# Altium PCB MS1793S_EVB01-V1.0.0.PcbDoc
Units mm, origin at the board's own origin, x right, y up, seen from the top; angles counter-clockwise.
Board outline 52.93 x 27.69 mm, 2 copper layers (Top Layer, Bottom Layer); 34 components, 26 nets, 126 pads, 278 vias.
Unrouted connection lines stored in the file: 2.
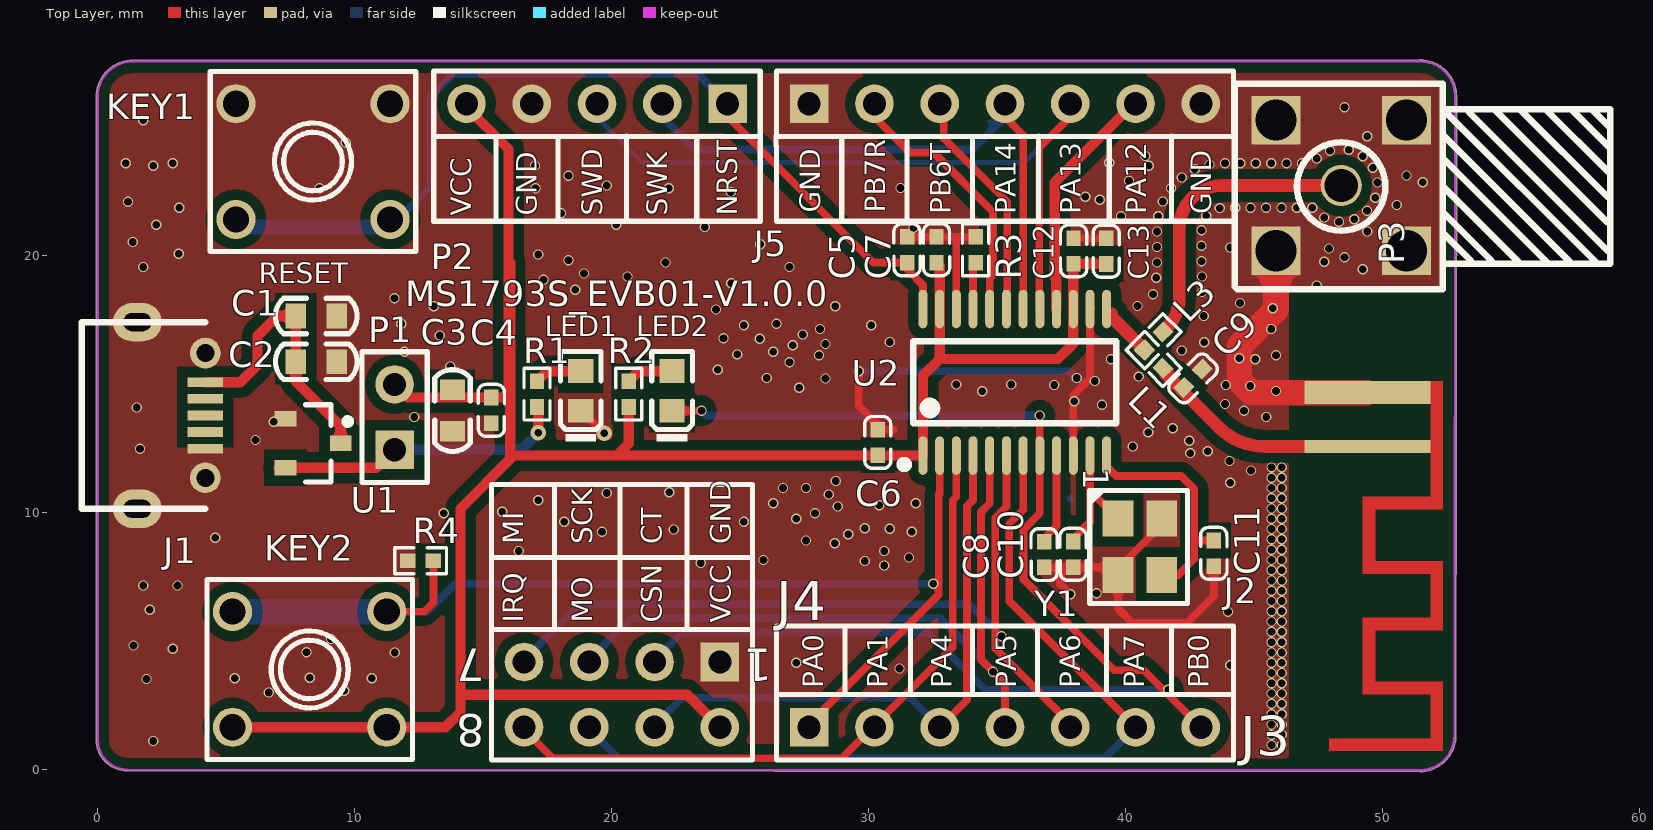
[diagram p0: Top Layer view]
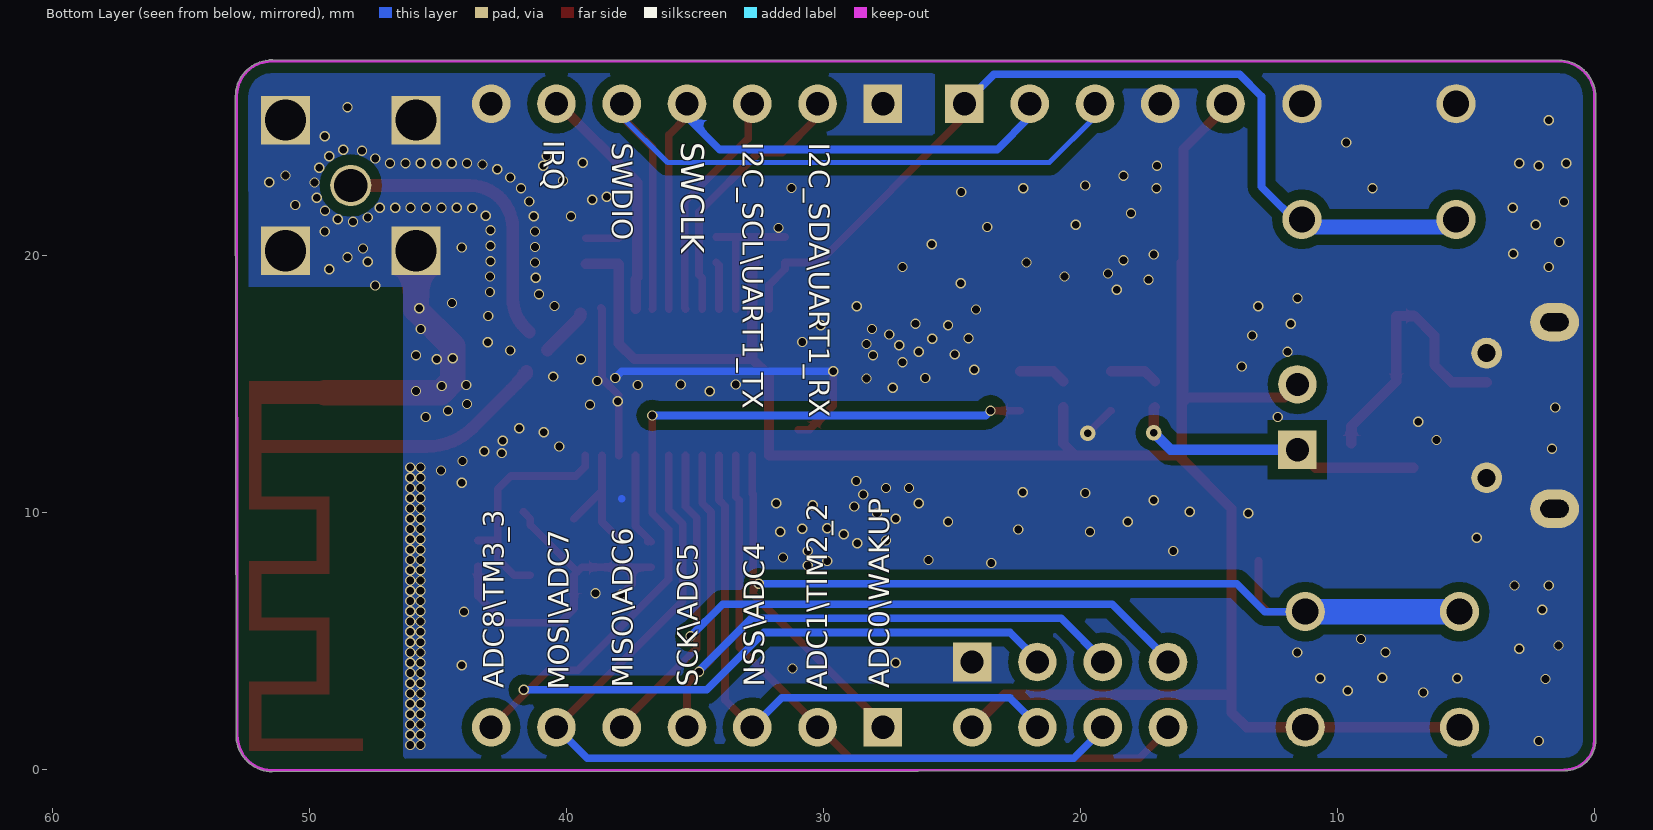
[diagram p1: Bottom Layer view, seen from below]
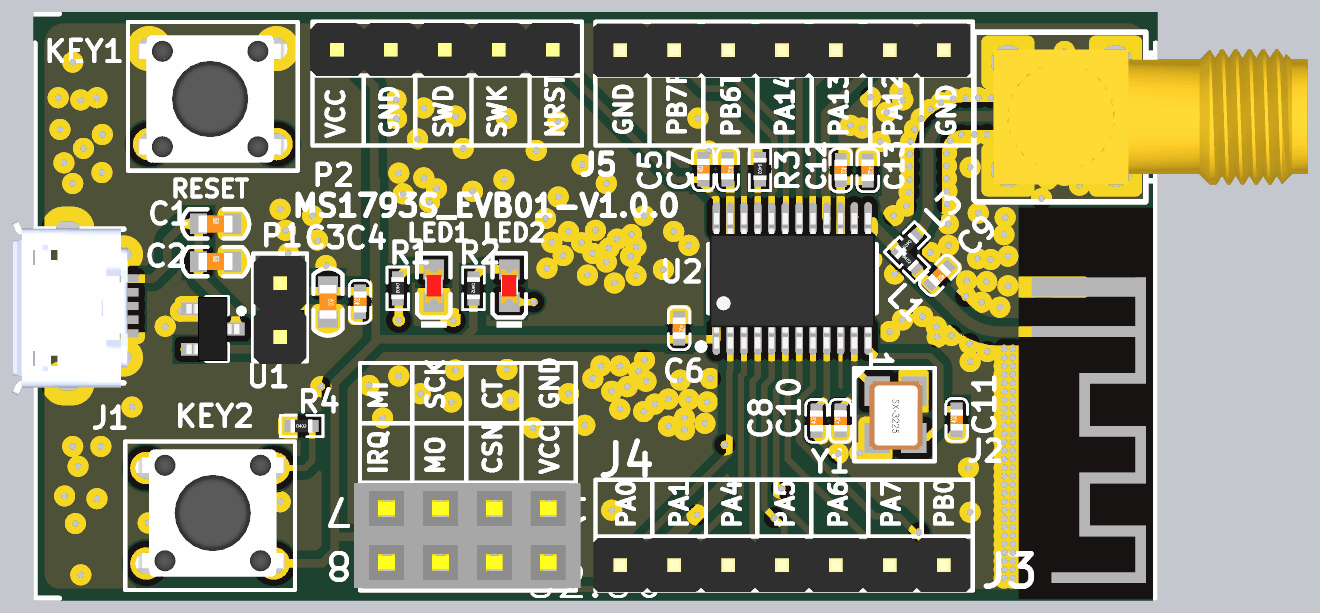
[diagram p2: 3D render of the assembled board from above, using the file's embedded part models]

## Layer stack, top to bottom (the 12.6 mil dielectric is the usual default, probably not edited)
Top Solder: solder mask 0.0102, Solder Resist, Dk 3.5
Top Layer: signal copper 0.0356
Dielectric 1: dielectric 0.32, FR-4, Dk 4.8
Bottom Layer: signal copper 0.0356
Bottom Solder: solder mask 0.0102, Solder Resist, Dk 3.5

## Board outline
-0.051,1.151 cw(c-0.001,1.151) -0.05,1.159 -0.051,26.162 cw(c-0.001,26.162) -0.051,26.168 cw(c1.366,26.188) 1.366,27.604 cw(c1.366,27.554) 1.372,27.604 51.428,27.609 cw(c51.429,27.559) 51.428,27.609 cw(c51.461,26.193) 51.493,27.609 51.562,27.609 cw(c51.562,27.559) 51.584,27.604 cw(c51.461,26.193) 52.877,26.193 cw(c52.827,26.193) 52.877,26.193 52.851,1.361 cw(c51.435,1.334) 52.851,1.334 cw(c51.435,1.334) 52.851,1.303 52.851,1.264 cw(c52.801,1.264) 52.849,1.25 cw(c51.435,1.334) 51.435,-0.083 cw(c51.435,-0.032) 51.435,-0.083 1.143,-0.051 cw(c1.143,0) 1.14,-0.051 cw(c1.151,1.151)

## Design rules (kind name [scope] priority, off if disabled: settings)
Clearance [All] p1: gap=0.25
ComponentClearance [All] p1 off: gap=0.254 collisioncheckmode=3 verticalgap=0.254 showdistances=FALSE
HoleToHoleClearance [All] p1: gap=0 allowstackedmicrovias=FALSE
MinimumSolderMaskSliver [All] p1 off: minsoldermaskwidth=0
PlaneConnect [All] p1: planeconnectstyle=Direct reliefexpansion=0.508 reliefentries=4 reliefconductorwidth=0.254 reliefairgap=0.254
PolygonConnect PolygonConnect_27 [All vs IsNamedPolygon('GND_L01_P042')] p1: connectstyle=Direct reliefconductorwidth=0.254 reliefentries=4 polygonreliefangle="90 Angle" airgapwidth=0.254
PolygonConnect PolygonConnect_26 [All vs IsNamedPolygon('GND_L02_P044')] p2: connectstyle=Direct reliefconductorwidth=0.254 reliefentries=4 polygonreliefangle="90 Angle" airgapwidth=0.254
PolygonConnect PolygonConnect_25 [All vs IsNamedPolygon('GND_L02_P026')] p3: connectstyle=Direct reliefconductorwidth=0.254 reliefentries=4 polygonreliefangle="90 Angle" airgapwidth=0.254
PolygonConnect PolygonConnect_24 [All vs IsNamedPolygon('GND_L01_P028')] p4: connectstyle=Direct reliefconductorwidth=0.254 reliefentries=4 polygonreliefangle="90 Angle" airgapwidth=0.254
PolygonConnect PolygonConnect_23 [All vs IsNamedPolygon('GND_L02_P022')] p5: connectstyle=Direct reliefconductorwidth=0.254 reliefentries=4 polygonreliefangle="90 Angle" airgapwidth=0.254
PolygonConnect PolygonConnect_22 [All vs IsNamedPolygon('GND_L01_P020')] p6: connectstyle=Direct reliefconductorwidth=0.254 reliefentries=4 polygonreliefangle="90 Angle" airgapwidth=0.254
PolygonConnect PolygonConnect_21 [All vs IsNamedPolygon('GND_L02_P016')] p7: connectstyle=Direct reliefconductorwidth=0.254 reliefentries=4 polygonreliefangle="90 Angle" airgapwidth=0.254
PolygonConnect PolygonConnect_20 [All vs IsNamedPolygon('GND_L01_P018')] p8: connectstyle=Direct reliefconductorwidth=0.254 reliefentries=4 polygonreliefangle="90 Angle" airgapwidth=0.254
PolygonConnect PolygonConnect_19 [All vs IsNamedPolygon('GND_L02_P014')] p9: connectstyle=Direct reliefconductorwidth=0.254 reliefentries=4 polygonreliefangle="90 Angle" airgapwidth=0.254
PolygonConnect PolygonConnect_18 [All vs IsNamedPolygon('GND_L01_P012')] p10: connectstyle=Direct reliefconductorwidth=0.254 reliefentries=4 polygonreliefangle="90 Angle" airgapwidth=0.254
PolygonConnect PolygonConnect_17 [All vs IsNamedPolygon('GND_L02_P010')] p11: connectstyle=Direct reliefconductorwidth=0.254 reliefentries=4 polygonreliefangle="90 Angle" airgapwidth=0.254
PolygonConnect PolygonConnect_16 [All vs IsNamedPolygon('GND_L01_P008')] p12: connectstyle=Direct reliefconductorwidth=0.254 reliefentries=4 polygonreliefangle="90 Angle" airgapwidth=0.254
PolygonConnect PolygonConnect_15 [All vs IsNamedPolygon('GND_L02_P010')] p13: connectstyle=Relief reliefconductorwidth=0.254 reliefentries=4 polygonreliefangle="45 Angle" airgapwidth=0.254
PolygonConnect PolygonConnect_14 [All vs IsNamedPolygon('GND_L01_P008')] p14: connectstyle=Relief reliefconductorwidth=0.254 reliefentries=4 polygonreliefangle="45 Angle" airgapwidth=0.254
PolygonConnect PolygonConnect_13 [All vs IsNamedPolygon('GND_L02_P010')] p15: connectstyle=Relief reliefconductorwidth=0.254 reliefentries=4 polygonreliefangle="45 Angle" airgapwidth=0.254
PolygonConnect PolygonConnect_12 [All vs IsNamedPolygon('GND_L01_P008')] p16: connectstyle=Relief reliefconductorwidth=0.254 reliefentries=4 polygonreliefangle="45 Angle" airgapwidth=0.254
PolygonConnect PolygonConnect_11 [All vs IsNamedPolygon('GND_L02_P006')] p17: connectstyle=Direct reliefconductorwidth=0.254 reliefentries=4 polygonreliefangle="90 Angle" airgapwidth=0.254
PolygonConnect PolygonConnect_10 [All vs IsNamedPolygon('GND_L01_P004')] p18: connectstyle=Direct reliefconductorwidth=0.254 reliefentries=4 polygonreliefangle="90 Angle" airgapwidth=0.254
PolygonConnect PolygonConnect_9 [All vs IsNamedPolygon('GND_L01_P004')] p19: connectstyle=Relief reliefconductorwidth=0.254 reliefentries=4 polygonreliefangle="45 Angle" airgapwidth=0.254
PolygonConnect PolygonConnect_8 [All vs IsNamedPolygon('GND_L02_P006')] p20: connectstyle=Relief reliefconductorwidth=0.254 reliefentries=4 polygonreliefangle="45 Angle" airgapwidth=0.254
PolygonConnect PolygonConnect_7 [All vs IsNamedPolygon('GND_L01_P004')] p21: connectstyle=Relief reliefconductorwidth=0.254 reliefentries=4 polygonreliefangle="45 Angle" airgapwidth=0.254
PolygonConnect PolygonConnect_6 [All vs IsNamedPolygon('GND_L02_P006') Or  IsNamedPolygon('GND_L01_P004')] p22: connectstyle=Relief reliefconductorwidth=0.254 reliefentries=4 polygonreliefangle="45 Angle" airgapwidth=0.254
PolygonConnect PolygonConnect_5 [All vs IsNamedPolygon('GND_L01_P000')] p23: connectstyle=Direct reliefconductorwidth=0.254 reliefentries=4 polygonreliefangle="90 Angle" airgapwidth=0.254
PolygonConnect PolygonConnect_4 [All vs IsNamedPolygon('GND_L02_P002')] p24: connectstyle=Direct reliefconductorwidth=0.254 reliefentries=4 polygonreliefangle="90 Angle" airgapwidth=0.254
PolygonConnect PolygonConnect_3 [All vs IsNamedPolygon('GND_L01_P002')] p25: connectstyle=Direct reliefconductorwidth=0.254 reliefentries=4 polygonreliefangle="90 Angle" airgapwidth=0.254
PolygonConnect PolygonConnect_2 [All vs IsNamedPolygon('GND_L02_P000')] p26: connectstyle=Direct reliefconductorwidth=0.254 reliefentries=4 polygonreliefangle="90 Angle" airgapwidth=0.254
PolygonConnect PolygonConnect_1 [All vs IsNamedPolygon('GND_L02_P000')] p27: connectstyle=Direct reliefconductorwidth=0.254 reliefentries=4 polygonreliefangle="90 Angle" airgapwidth=0.254
PolygonConnect [All] p28: connectstyle=Relief reliefconductorwidth=0.254 reliefentries=4 polygonreliefangle="90 Angle" airgapwidth=0.254
RoutingVias [All] p1: holewidth=0.3 width=0.6 viastyle="Through Hole" minholewidth=0.3 minwidth=0.3 maxholewidth=0.711 maxwidth=1.27
SilkToSilkClearance [All] p1 off: silktosilkclearance=0
SilkToSolderMaskClearance [IsPad] p1 off: minsilkscreentomaskgap=0 clearancetoexposedcopper=TRUE
SolderMaskExpansion [All] p1: expansion=0.3
Width [All] p1: maxlimit=1 minlimit=0.1 preferedwidth=0.2
23 further rules are at their usual default settings.

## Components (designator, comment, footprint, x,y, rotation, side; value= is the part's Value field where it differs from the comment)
C1 "47uF" c0603 8.509,17.647 r0 top
C2 "0.1uF" c0603 8.509,15.869 r0 top
C3 "10uF" C0603 13.809,13.97 r270 top
C4 "0.1uF" C0402 15.321,14.478 r90 top
C5 "0.1uF" C0402 31.496,20.726 r90 top
C6 "10uF" C0402 30.353,12.226 r270 top
C7 "0.01uF" C0402 32.639,19.726 r270 top
C8 "10uF" C0402 36.83,8.868 r90 top
C9 "NC" C0402 42.268,14.87 r225 top
C10 "15pF" C0402 37.962,8.875 r90 top
C11 "15pF" C0402 43.434,8.915 r90 top
C12 "1uF" C0402 37.973,19.679 r270 top
C13 "0.1uF" C0402 39.243,19.668 r270 top
J1 "USB-Micro" USB-MICRO 4.191,13.778 r90 top
J2 "ANTENNA--F" ANT-2 49.403,12.567 r270 top
J3 "MG127" HDR1X7 27.686,1.645 r0 top
J4 "24L01" HDR2X4 24.211,4.185 r180 top
J5 "MG127" HDR1X7 27.686,25.908 r0 top
KEY1 "Button" SW_DIP 8.382,23.658 r90 top
KEY2 "Button" SW_DIP 8.251,3.895 r270 top
L1 "0R" R0402 41.446,15.621 r315 top
L3 "0R" R0402 40.739,16.319 r225 top
LED1 "LED2" LED_0603 18.796,14.731 r90 top
LED2 "LED2" LED_0603 22.352,14.731 r90 top
P1 "Header 2" HDR1X2 11.554,12.446 r90 top
P2 "JLink-SWD" HDR1X5 24.511,25.908 r180 top
P3 "SMA_FLAT" SMA-KWE 45.847,20.187 r0 top
R1 "2K" R0402 17.095,14.107 r270 top
R2 "2K" R0402 20.662,14.107 r270 top
R3 "4.7K" R0402 34.163,19.726 r270 top
R4 "4.7K" R0402 13.065,8.122 r0 top
U1 "SGM2300" SOT23_L 8.382,12.694 r0 top
U2 "MS1793S" TSSOP-24 35.687,15.069 r0 top
Y1 "16MHz 12pF 20ppm" XT3225 39.302,10.262 r270 top

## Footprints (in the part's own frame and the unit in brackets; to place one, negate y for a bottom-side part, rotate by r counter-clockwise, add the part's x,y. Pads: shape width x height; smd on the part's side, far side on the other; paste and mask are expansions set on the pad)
ANT-2 [mm]
  rect 0.5x4.9 smd: 1(0,0)
  rect 0.9x4.9 smd: 2(-2.1,0)
  Top Layer region: -0.25,-2.45 0.25,-2.45 0.25,2.45 -0.25,2.45
  Top Layer region: 11.35,-1.49 11.85,-1.49 11.85,2.45 11.35,2.45
  Top Layer region: 9.15,2.45 11.85,2.45 11.85,2.95 9.15,2.95
  Top Layer region: 9.15,-0.188 9.65,-0.188 9.65,2.452 9.15,2.452
  Top Layer region: 7.15,-0.188 9.15,-0.188 9.15,0.312 7.15,0.312
  Top Layer region: 6.65,-0.188 7.15,-0.188 7.15,2.452 6.65,2.452
  Top Layer region: 4.45,2.45 7.15,2.45 7.15,2.95 4.45,2.95
  Top Layer region: 4.45,-0.19 4.95,-0.19 4.95,2.45 4.45,2.45
  Top Layer region: 2.45,-0.19 4.45,-0.19 4.45,0.31 2.45,0.31
  Top Layer region: 1.95,-0.19 2.45,-0.19 2.45,2.45 1.95,2.45
  Top Layer region: -2.55,2.45 2.45,2.45 2.45,2.95 -2.55,2.95
  Top Layer region: -2.548,-2.45 -1.648,-2.45 -1.648,2.45 -2.548,2.45
C0402 [mil]
  rect 24x22 smd: 1(0,0) 2(-39.37,0)
  silkscreen extent -59,-20 20,20, body extent -40,-12 0,12, height 8
c0603 [mm]
  rect 0.8x0.965 smd: 1(-0.8,0) 2(0.8,0)
  silkscreen extent -1.59,-0.69 1.59,0.69, body extent -0.8,-0.4 0.8,0.4, height 0.3
C0603 [mm]
  rect 0.8x0.965 smd: 1(-0.8,0) 2(0.8,0)
  silkscreen extent -1.59,-0.69 1.59,0.69, body extent -0.8,-0.4 0.8,0.4, height 0.3
HDR1X2 [mm] "Connector; Header; 2 Position"
  rect 1.5x1.5 hole 0.9: 1(0,0)
  round 1.5 hole 0.9: 2(2.54,0)
  silkscreen extent -1.27,-1.27 3.81,1.27, body extent -1.4,-1.24 3.68,1.24, height 8.54
HDR1X5 [mm] "Connector; Header; 5 Position"
  rect 1.5x1.5 hole 0.9: 1(0,0)
  round 1.5 hole 0.9: 2(2.54,0) 3(5.08,0) 4(7.62,0) 5(10.16,0)
  silkscreen extent -1.27,-1.27 11.43,1.27, body extent -1.15,-1.2 11.55,1.29, height 8.54
HDR1X7 [mm] "Connector; Header; 7 Position"
  rect 1.5x1.5 hole 0.9: 1(0,0)
  round 1.5 hole 0.9: 2(2.54,0) 3(5.08,0) 4(7.62,0) 5(10.16,0) 6(12.7,0) 7(15.24,0)
  silkscreen extent -1.27,-1.27 16.51,1.27, body extent -1.37,-1.35 16.41,1.19, height 8.54
HDR2X4 [mm] "Connector; Header; 4x2 Position"
  rect 1.5x1.5 hole 0.9: 1(0,0)
  round 1.5 hole 0.9: 2(0,2.54) 3(2.54,0) 4(2.54,2.54) 5(5.08,0) 6(5.08,2.54) 7(7.62,0) 8(7.62,2.54)
  silkscreen extent -1.27,-1.27 8.89,3.81, body extent -1.5,-1.26 9.17,3.7, height 8.3
LED_0603 [mm]
  rect 0.93x0.98 smd: 1(0.77,0) 2(-0.77,0)
  silkscreen extent -1.98,-0.79 1.54,0.79, body extent -0.8,-0.4 0.8,0.4, height 0.6
R0402 [mil]
  rect 24x22 smd: 1(0,0) 2(-39.37,0)
  silkscreen extent -59,-20 20,20, body extent -40,-12 0,12, height 13
SMA-KWE [mm]
  round 1.6 hole 1.3: 1(2.54,2.54)
  rect 1.9x1.9 hole 1.6: 2(0,0) 2(0,5.08) 2(5.08,0) 2(5.08,5.08)
  silkscreen extent -1.6,-1.5 13,6.5, body extent -0.67,-0.68 14.12,5.67, height 9.57
SOT23_L [mm]
  rect 0.85x0.6 smd: 1(-1.075,0.95) 2(-1.075,-0.95) 3(1.075,0)
  silkscreen extent -0.3,-1.5 1.48,1.5, body extent -1.25,-1.5 1.25,1.5, height 1.05
SW_DIP [mil]
  round 60 hole 40: 1(88.58,118.11) 2(88.58,-118.11) 3(-88.58,-118.11) 4(-88.58,118.11)
  silkscreen extent -138,-157 138,157, body extent -123,-157 113,167, height 291
TSSOP-24 [mm]
  oval 0.35x1.5 smd: 1(-3.575,-2.85) 2(-2.925,-2.85) 3(-2.275,-2.85) 4(-1.625,-2.85) 5(-0.975,-2.85) 6(-0.325,-2.85) 7(0.325,-2.85) 8(0.975,-2.85) 9(1.625,-2.85) 10(2.275,-2.85) 11(2.925,-2.85) 12(3.575,-2.85) 13(3.575,2.85) 14(2.925,2.85) 15(2.275,2.85) 16(1.625,2.85) 17(0.975,2.85) 18(0.325,2.85) 19(-0.325,2.85) 20(-0.975,2.85) 21(-1.625,2.85) 22(-2.275,2.85) 23(-2.925,2.85) 24(-3.575,2.85)
  silkscreen extent -4.45,-3.35 3.95,1.6, body extent -3.9,-3.3 3.9,3.1, height 1.2
USB-MICRO [mil]
  oval 59.06x74.8 hole 27.56 slot 43.31 at 90 deg: 0(-143,104) 0(143,104)
  round 47.24 hole 27.5: 0(-95.5,0) 0(95.5,0)
  rect 15x54 smd: 1(51,0) 2(25.5,0) 3(0,0) 4(-25.5,0) 5(-51,0)
  silkscreen extent -143,0 143,189, body extent -165,-7 158,207, height 97
XT3225 [mm]
  rect 1.4x1.2 smd: 1(0.5,0.4) 2(2.7,0.4) 3(2.7,2.1) 4(0.5,2.1)
  silkscreen extent -0.6,-0.7 3.8,3.1, body extent -0.1,-0.1 3.3,2.6, height 0.81

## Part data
C1 C2 C3 C4 C5 C6 C7 C8 C9 C10 C11 C12 C13: library part CAP, "Capacitor"
J2: library part ANT
J3 J5: library part "Header 7", "Header, 7-Pin"
J4: library part "Header 4X2", "Header, 4-Pin, Dual row"
KEY1 KEY2: library part KEY-4
L1 L3: library part Res2, "Resistor"
LED1 LED2: "Typical RED, GREEN, YELLOW, AMBER GaAs LED"
P1: "Header, 2-Pin"
P2: library part "Header 5", "Header, 5-Pin"
R1 R2 R3 R4: library part R
U2: "BLE"
Y1: library part XTAL3225

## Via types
v1: diameter 0.4, hole 0.3, Top Layer to Bottom Layer, 276 vias
v2: diameter 0.6, hole 0.3, Top Layer to Bottom Layer, 2 vias

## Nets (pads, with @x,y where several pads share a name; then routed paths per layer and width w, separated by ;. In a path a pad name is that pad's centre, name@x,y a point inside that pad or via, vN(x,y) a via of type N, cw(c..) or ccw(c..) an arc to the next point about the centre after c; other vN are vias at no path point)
GND: C1.2 C2.2 C3.2 C4.2 C5.1 C6.2 C7.2 C8.2 C9.2 C10.2 C11.2 C12.2 C13.2 J1.0 J1.5 J2.2 J4.1 J5.1 J5.7 KEY1.1 KEY1.2 LED1.2 P2.4 P3.2 R3.2 R4.2 U1.1 U2.10 U2.14 U2.22 Y1.2 Y1.4 | length 51.4
  Top Layer w0.3: LED1.2 18.829,13.961 v2(19.709,13.081) ; v1(29.614,15.496) 29.614,14.153 30.541,13.226 30.982,13.226 ; C5.1 C7.2 ; U2.22 33.412,20.654 33.341,20.726 C7.2 ; R3.2 C7.2 ; C8.2@36.703,7.868 C8.2 37.448,7.868 ; v1(37.846,6.826) 37.448,7.224 37.448,7.868 ; U2.10 v1@37.962,14.315 ; 37.962,14.566 38.612,15.216 U2.14 U2.14@38.652,17.959 ; C12.2 37.984,20.668 C13.2 ; Y1.4@41.667,10.027 Y1.4 41.402,9.519 Y1.2@39.573,7.69 ; C11.2 43.434,6.747 42.396,5.709 40.259,5.709 39.702,6.266 Y1.2 Y1.2@39.573,7.69 ; 37.448,7.868 39.396,7.868 Y1.2@39.573,7.69
  Top Layer w1: P3.2@45.847,20.187 45.847,17.901 44.419,16.473 44.419,15.14 44.891,14.667 J2.2
  Bottom Layer w0.3: v1(29.614,15.496) 37.838,15.496 v1(38.1,15.234)
  other v1: 45.675,0.957 46.075,0.957 2.159,1.11 45.675,1.357 46.075,1.357 45.675,1.757 46.075,1.757 45.675,2.157 46.075,2.157 45.675,2.557 46.075,2.557 45.675,2.957 46.075,2.957 6.656,3.002 9.592,3.065 45.675,3.357 46.075,3.357 1.905,3.527 5.334,3.556 10.668,3.55 8.251,3.573 45.675,3.757 46.075,3.757 31.198,3.931 44.069,4.058 27.178,4.157 45.675,4.157 46.075,4.157 11.557,4.555 45.675,4.557 46.075,4.557 8.128,4.566 2.921,4.699 1.397,4.826 45.675,4.957 46.075,4.957 9.082,5.08 45.675,5.357 46.075,5.357 45.675,5.757 46.075,5.757 43.985,6.145 45.675,6.157 46.075,6.157 2.032,6.223 45.675,6.557 46.075,6.557 38.869,6.861 45.675,6.957 46.075,6.957 1.778,7.16 3.105,7.16 45.675,7.357 46.075,7.357 45.675,7.757 46.075,7.757 30.607,7.941 23.466,8.034 29.849,8.117 25.908,8.157 45.675,8.157 46.075,8.157 31.57,8.249 16.383,8.503 30.607,8.503 45.675,8.557 46.075,8.557 28.684,8.802 27.559,8.915 45.675,8.957 46.075,8.957 4.572,9.017 29.21,9.156 19.627,9.251 31.679,9.258 22.413,9.339 45.675,9.357 46.075,9.357 30.817,9.375 29.845,9.392 18.161,9.646 25.146,9.646 27.178,9.757 45.675,9.757 46.075,9.757 13.472,9.977 27.916,9.977 15.748,10.033 45.675,10.157 46.075,10.157 28.795,10.233 30.412,10.287 26.289,10.36 31.829,10.362 17.145,10.478 45.675,10.557 46.075,10.557 28.448,10.706 19.812,10.762 22.245,10.789 26.67,10.957 27.559,10.957 45.675,10.957 46.075,10.957 44.069,11.16 28.723,11.229 45.675,11.357 46.075,11.357 44.878,11.633 45.675,11.757 46.075,11.757 44.042,12.003 42.519,12.313 43.193,12.39 1.651,12.483 40.275,12.573 42.473,12.795 6.139,12.821 40.883,13.123 41.832,13.281 6.858,13.532 12.319,13.716 45.466,13.719 44.605,13.956 1.524,14.091 39.077,14.198 43.862,14.223 38,14.331 34.417,14.719 45.847,14.731 27.305,14.859 44.846,14.926 37.223,14.962 43.9,14.962 33.412,14.986 35.547,14.986 38.802,15.115 28.321,15.216 26.035,15.234 40.513,15.29 24.13,15.56 13.716,15.685 26.924,15.849 39.429,15.967 45.038,15.967 44.419,16.006 28.067,16.123 45.847,16.123 24.892,16.154 11.938,16.256 26.289,16.256 42.185,16.304 27.051,16.51 28.321,16.558 30.817,16.637 43.053,16.631 25.758,16.758 24.354,16.778 13.316,16.885 27.432,16.929 28.109,17.145 45.662,17.139 25.146,17.284 30.099,17.286 11.811,17.344 26.416,17.344 43.037,17.647 24.06,17.901 45.72,17.949 13.081,18.028 28.702,18.028 40.459,18.034 44.45,18.155 11.554,18.336 41.067,18.489 42.975,18.583 18.59,18.666 47.435,18.836 24.66,18.917 17.353,19.063 41.193,19.133 20.62,19.183 42.971,19.183 18.923,19.298 49.222,19.472 1.778,19.552 26.924,19.552 22.098,19.733 41.217,19.733 47.724,19.756 42.951,19.783 18.321,19.819 48.514,19.933 17.145,20.041 3.155,20.066 47.913,20.273 41.217,20.333 44.069,20.314 42.951,20.383 25.781,20.441 1.366,20.526 41.217,20.933 49.403,20.933 42.951,20.983 31.743,21.076 23.622,21.112 2.286,21.203 20.18,21.203 48.301,21.314 48.894,21.409 47.724,21.48 39.82,21.531 41.267,21.531 43.137,21.553 18.027,21.648 49.394,21.741 43.661,21.846 3.175,21.86 44.261,21.86 44.861,21.86 45.461,21.86 46.061,21.86 46.661,21.86 47.261,21.86 50.546,21.965 1.179,22.098 41.446,22.103 38.989,22.166 49.716,22.247 38.427,22.292 24.638,22.473 8.636,22.614 17.038,22.614 22.225,22.614 41.761,22.614 31.242,22.632 19.812,22.727 49.796,22.841 51.562,22.854 40.132,22.91 42.185,23.039 18.321,23.108 50.927,23.117 42.693,23.357 49.618,23.414 2.159,23.489 17.018,23.489 40.894,23.489 43.265,23.54 1.097,23.594 2.921,23.594 43.862,23.594 44.462,23.594 45.062,23.594 45.662,23.594 46.262,23.594 46.862,23.594 39.363,23.616 47.435,23.773 40.767,23.87 49.222,23.866 47.954,24.074 48.676,24.113 9.652,24.4 49.403,24.645 1.778,25.267 48.514,25.775
NetC8_1: C8.1 U2.9 | length 3.7
  Top Layer w0.3: C8.1@36.703,8.868 C8.1@36.83,8.995 ; C8.1 C8.1@36.83,8.995 ; U2.9 37.312,9.477 C8.1@36.83,8.995
NetC9_1: C9.1 J2.1 L1.1 | length 9.4
  Top Layer w0.5: L1.1@41.549,15.494 41.549,15.392 42.17,14.772 43.63,13.311 ccw(c45.426,15.107) 45.426,12.567 J2.1 J2.1@49.784,12.567
NetC10_1: C10.1 U2.11 Y1.1 | length 5.2
  Top Layer w0.3: C10.1@37.846,8.868 38.612,9.634 38.612,10.852 ; U2.11 38.612,10.852 ; Y1.1 38.612,10.852
NetC11_1: C11.1 U2.12 Y1.3 | length 9.2
  Top Layer w0.3: U2.12 39.262,11.792 39.63,11.424 42.164,11.424 42.672,10.916 42.672,8.995 ; Y1.3 42.037,7.562 42.672,8.197 42.672,8.995 ; C11.1 42.752,8.915 42.672,8.995
NetL1_2: L1.2 L3.1 U2.13 | length 1.9
  Top Layer w0.5: 39.454,17.731 ccw(c39.739,17.731) 39.537,17.53 L1.2
NetL3_2: L3.2 P3.1 | length 11.5
  Top Layer w0.5: L3.2 41.599,17.179 ccw(c40.428,18.35) 42.084,18.35 42.084,21.047 cw(c43.764,21.047) 42.371,21.987 cw(c43.764,21.047) 43.764,22.727 P3.1
NetLED1_1: LED1.1 R1.2 | length 1.9
  Top Layer w0.4: R1.2 17.489,15.501 LED1.1
NetLED2_1: LED2.1 R2.2 | length 1.9
  Top Layer w0.4: R2.2 21.056,15.501 LED2.1
NetR3_1: R3.1 U2.21 | length 1.8
  Top Layer w0.3: U2.21 34.062,19.625 R3.1
NRST: C5.2 KEY1.3 KEY1.4 P2.1 U2.24 | length 35.5
  Top Layer w0.3: P2.1@24.511,25.394 30.18,19.726 C5.2 31.496,19.472 32.112,18.856 U2.24
  Bottom Layer w0.3: KEY1.3@11.382,21.112 12.954,22.684 12.954,26.203 13.809,27.058 23.361,27.058 P2.1
  Bottom Layer w0.6: KEY1.4@5.382,21.112 KEY1.3@11.382,21.112
PA0: J3.1 KEY2.3 KEY2.4 R4.1 U2.2 | length 44
  Top Layer w0.3: KEY2.4 12.714,6.145 13.065,6.497 R4.1 ; J3.1 27.686,1.772 32.724,6.81 32.724,6.979 ; 32.702,7 32.724,6.979 ; U2.2 32.762,10.744 32.724,10.706 32.724,6.979
  Bottom Layer w0.3: KEY2.4 12.827,6.145 13.915,7.233 v1(32.512,7.233)
  Bottom Layer w1: KEY2.3 KEY2.4
PA1: J3.2 J4.8 U2.3 | length 26.6
  Top Layer w0.3: J4.8@16.51,1.647 17.713,0.444 28.956,0.444 33.274,4.762 33.274,10.478 33.412,10.616 U2.3
PA4: J3.3 J4.4 U2.4 | length 23.2
  Top Layer w0.3: J3.3 33.824,2.703 33.824,10.25 34.062,10.488 U2.4
  Bottom Layer w0.3: J4.4@21.59,1.647 22.74,2.797 31.614,2.797 J3.3
PA5: J3.4 J4.5 U2.5 | length 28.5
  Top Layer w0.3: U2.5 34.712,10.36 34.374,10.022 34.374,4.273 v1(34.842,3.804) 35.306,3.341 J3.4
  Bottom Layer w0.3: J4.5@19.05,4.187 20.75,5.887 32.795,5.887 v1@34.86,3.822
PA6: J3.5 J4.7 U2.6 | length 32.1
  Top Layer w0.3: U2.6 35.362,10.233 34.924,9.794 34.924,5.836 34.924,4.713 37.846,1.79 J3.5
  Bottom Layer w0.3: J4.7@16.51,4.187 18.76,6.437 33.916,6.437 v1(35.17,5.183)
PA7: J3.6 J4.6 U2.7 | length 35.2
  Top Layer w0.3: U2.7 36.012,10.105 35.474,9.566 35.474,6.558 J3.6
  Bottom Layer w0.3: J4.6@19.05,1.647 20.253,0.444 39.185,0.444 J3.6
PA12_IRQ: J5.6 U2.16 | length 9.4
  Top Layer w0.4: U2.16 37.296,17.935 37.296,19.091 37.244,19.143 37.244,22.847 40.305,25.908 J5.6
PA13-SWDIO: J5.5 P2.3 U2.17 | length 27.9
  Top Layer w0.3: U2.17 36.644,17.937 36.644,24.192 J5.5@37.846,25.394
  Bottom Layer w0.2: P2.3@19.431,25.394 21.209,23.616 36.068,23.616 J5.5@37.846,25.394
PA14-SWCLK: J5.4 P2.2 U2.18 | length 22.2
  Top Layer w0.3: J5.4@35.306,25.394 36.012,24.688 U2.18
  Bottom Layer w0.3: P2.2@21.971,25.394 23.241,24.124 34.036,24.124 J5.4@35.306,25.394
PB0: J3.7 J4.3 LED2.2 U2.8 | length 51.8
  Top Layer w0.3: LED2.2@22.352,13.956 23.487,13.956 v1(23.495,13.964) ; v1(36.662,13.778) U2.8 36.662,9.977 36.024,9.339 36.024,7.398 39.557,3.864 40.707,3.864 J3.7
  Bottom Layer w0.3: J4.3@21.59,4.187 22.74,5.337 32.306,5.337 34.539,3.104 v1(41.656,3.104) ; v1(23.495,13.964) 23.681,13.778 v1(36.662,13.778)
PB6-TX: J5.3 U2.19 | length 8.6
  Top Layer w0.3: J5.3@32.766,25.394 32.926,25.234 32.926,24.558 35.392,22.092 35.392,17.949 U2.19
PB7-RX: J5.2 U2.20 | length 10
  Top Layer w0.3: J5.2@30.226,25.394 31.611,24.009 32.524,24.009 34.842,21.691 34.842,19.255 34.712,19.125 U2.20
VBUS: C1.1 C2.1 J1.1 U1.3 | length 10.9
  Top Layer w0.4: J1.1 5.554,15.074 6.223,15.742 6.223,16.885 6.985,17.647 C1.1 C2.1 7.709,15.107 9.457,13.359 U1.3
VCC: C3.1 C4.1 C6.1 C7.1 C12.1 C13.1 J4.2 KEY2.1 KEY2.2 P1.2 P2.5 R2.1 U2.1 U2.15 U2.23 | length 90.9
  Top Layer w0.4: KEY2.2 KEY2.1 13.533,1.645 14.122,2.234 14.122,2.915 ; P1.2 12.062,14.478 C4.1 15.828,14.478 15.987,14.319 15.987,19.791 ; P2.5 14.351,25.782 15.987,24.146 15.987,19.791 ; R2.1 20.662,12.688 20.193,12.219 ; J4.2 22.941,2.915 14.122,2.915 ; C7.1 32.762,19.603 U2.23 32.762,15.976 ; C13.1 39.232,19.679 C12.1 37.962,19.668 U2.15 37.962,16.576 37.362,15.976 32.762,15.976 ; 14.122,2.915 14.122,10.157 16.05,12.086 ; 15.987,19.791 16.05,19.728 16.05,12.086 ; 16.05,12.086 16.184,12.219 20.193,12.219 ; 20.193,12.219 U2.1 32.112,15.326 32.762,15.976
VCC_3V: P1.1 R1.1 U1.2 | length 11.7
  Top Layer w0.4: U1.2@7.051,11.744 U1.2 10.852,11.744 P1.1 ; R1.1 17.145,14.057 v2(17.145,13.109)
  Bottom Layer w0.4: P1.1 16.482,12.446 v2(17.145,13.109)
pads on no net: J1.2 J1.3 J1.4

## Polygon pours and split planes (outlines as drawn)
GND on Bottom Layer "GND_L02_P044" (solid, remove dead copper, pour order 44): 1.27,27.559 1.143,27.432 0.762,27.432 0.127,26.797 0.127,26.543 -0.001,26.415 -0.001,1.524 -0.001,1.361 -0.001,0.957 0.254,0.508 0.508,0.254 0.884,-0.021 45.847,-0.021 46.355,-0.021 46.355,18.796 52.801,18.796 52.801,26.416 52.705,26.511 52.705,26.797 52.07,27.432 51.816,27.432 51.689,27.559 1.143,27.559
GND on Top Layer "GND_L01_P042" (solid, remove dead copper, pour order 42): 1.27,27.559 1.143,27.432 0.762,27.432 0.127,26.797 0.127,26.543 -0.001,26.415 -0.001,1.524 -0.001,1.403 -0.001,0.963 0.26,0.508 0.508,0.26 0.884,-0.015 46.355,-0.015 46.355,0.481 46.355,18.796 52.801,18.796 52.801,26.416 52.705,26.511 52.705,26.797 52.07,27.432 51.816,27.432 51.689,27.559 1.143,27.559

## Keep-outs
Keep-Out Layer:
  lines w0.1: -0.001,1.151 ccw(c1.151,1.151) 1.177,0 ; -0.001,26.162 0,1.151 ; 0,26.156 cw(c1.366,26.188) 1.366,27.554 ; 1.143,0 51.435,-0.032 ccw(c51.435,1.334) 52.801,1.365 ; 1.366,27.553 51.562,27.559 ; 51.429,27.559 cw(c51.461,26.193) 52.827,26.193 52.801,1.264

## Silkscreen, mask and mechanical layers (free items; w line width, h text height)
Top Overlay:
  lines w0.2: 13.081,24.765 13.081,21.336 25.781,21.336 25.781,24.688 ; 15.321,5.455 15.321,11.094 16.129,11.094 ; 15.321,8.249 25.4,8.249 ; 15.35,11.094 25.4,11.094 ; 15.494,21.409 15.494,24.632 ; 17.78,5.461 17.78,11.094 ; 17.915,21.336 17.915,24.632 ; 20.32,5.522 20.32,11.049 ; 20.574,21.336 20.574,24.645 ; 22.93,5.461 22.93,11.094 ; 23.241,24.638 23.31,24.638 23.31,21.336 ; 25.019,11.094 25.481,11.094 25.481,5.201 ; 26.4,24.284 26.4,24.654 ; 26.416,2.794 26.416,5.588 44.196,5.588 44.196,2.557 ; 26.416,24.267 26.416,21.336 44.247,21.336 ; 28.953,21.409 28.953,24.632 ; 29.083,2.915 29.083,5.588 ; 31.496,21.336 31.496,24.632 ; 31.623,2.915 31.623,5.588 ; 34.036,2.915 34.036,5.588 ; 34.036,21.403 34.036,24.632 ; 36.576,2.915 36.576,5.588 ; 36.606,21.336 36.606,24.645 ; 39.262,2.921 39.262,5.588 ; 39.362,21.409 39.362,24.632 ; 41.783,2.915 41.783,5.588 ; 41.783,21.336 41.783,24.645
  text "GND" at 28.109,21.662 h0.8 r90
  text "PB7R" at 30.647,21.662 h0.8 r90
  text "PB6T" at 33.185,21.612 h0.8 r90
  text "PA14" at 35.723,21.612 h0.8 r90
  text "PA13" at 38.261,21.612 h0.8 r90
  text "PA12" at 40.799,21.612 h0.8 r90
  text "GND" at 43.337,21.612 h0.8 r90
  text "VCC" at 14.547,21.553 h0.8 r90
  text "GND" at 17.087,21.553 h0.8 r90
  text "SWD" at 19.627,21.553 h0.8 r90
  text "SWK" at 22.167,21.553 h0.8 r90
  text "NRST" at 24.892,21.553 h0.8 r90
  text "RESET" at 6.271,18.923 h0.8
  text "MS1793S_EVB01-V1.0.0" at 11.968,18.028 h1
  text "MI" at 16.556,8.757 h0.8 r90
  text "SCK" at 19.25,8.757 h0.8 r90
  text "CT" at 21.952,8.757 h0.8 r90
  text "GND" at 24.638,8.757 h0.8 r90
  text "IRQ" at 16.556,5.709 h0.8 r90
  text "MO" at 19.25,5.709 h0.8 r90
  text "CSN" at 21.944,5.709 h0.8 r90
  text "VCC" at 24.638,5.709 h0.8 r90
  text "PA0" at 28.243,3.169 h0.8 r90
  text "PA1" at 30.741,3.169 h0.8 r90
  text "PA4" at 33.239,3.169 h0.8 r90
  text "PA5" at 35.736,3.169 h0.8 r90
  text "PA6" at 38.234,3.169 h0.8 r90
  text "PA7" at 40.732,3.169 h0.8 r90
  text "PB0" at 43.229,3.169 h0.8 r90
Bottom Overlay:
  text "IRQ" at 40.881,24.488 h0.8 r90
  text "I2C_SCL\UART1_TX" at 33.137,24.4 h0.8 r90
  text "SWCLK" at 35.814,24.4 h1.52 r90
  text "I2C_SDA\UART1_RX" at 30.547,24.38 h0.8 r90
  text "SWDIO" at 38.214,24.38 h0.8 r90
  text "NSS\ADC4" at 32.296,3.213 h0.8 r270
  text "SCK\ADC5" at 34.892,3.213 h0.8 r270
  text "ADC0\WAKUP" at 27.432,3.166 h0.8 r270
  text "MISO\ADC6" at 37.425,3.176 h0.8 r270
  text "ADC8\TM3_3" at 42.446,3.173 h0.8 r270
  text "ADC1\TIM2_2" at 29.84,3.087 h0.8 r270
  text "MOSI\ADC7" at 39.906,3.11 h0.8 r270
Top Solder:
  rectangle: 46.355,-0.032 52.832,18.409
Bottom Solder:
  rectangle: 46.355,-0.032 52.832,18.409

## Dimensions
1.143,0 to 1.366,27.553 on Top Overlay
-0.001,26.162 to 52.801,1.264 on Top Overlay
